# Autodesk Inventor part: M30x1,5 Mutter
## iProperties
Shininess: 64.0
Length Units: 11269
Angle Units: 11279
Time Units: 11290
Mass Units: 11283
Length Display Precision: 3
Angle Display Precision: 2
Compacted: True
Part Number: M30x1,5 Mutter
Document SubType Name: Modeling
Created: 2003-04
Material: Standard
Designer: li
Density: 0.0
Volumn: 0.0
Area: 0.0
PropertySet Name: Model Information
Control State: 0
Master: False
Checked Out: False
Author: li
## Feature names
1. Extrusion1
2. Fase1 [Chamfer]
3. Fase2 [Chamfer]
4. Extrusion2
5. Fase3 [Chamfer]
6. Fase4 [Chamfer]
7. Extrusion3
